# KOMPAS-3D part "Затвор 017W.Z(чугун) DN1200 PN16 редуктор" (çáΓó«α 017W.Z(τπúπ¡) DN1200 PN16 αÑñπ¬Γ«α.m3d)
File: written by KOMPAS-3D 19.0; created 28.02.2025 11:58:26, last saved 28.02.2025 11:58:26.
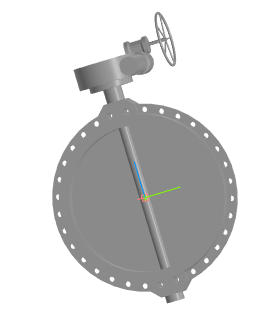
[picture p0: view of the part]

Document properties: Автор: Евгений; Полное имя файла: Затвор 017W.Z(чугун) DN1200 PN16 редуктор.a3d

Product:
- Part/product: Затвор 017W.Z(чугун) DN1200 PN16 редуктор
    Масса: 1592.58

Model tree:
1. Операция без истории:1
